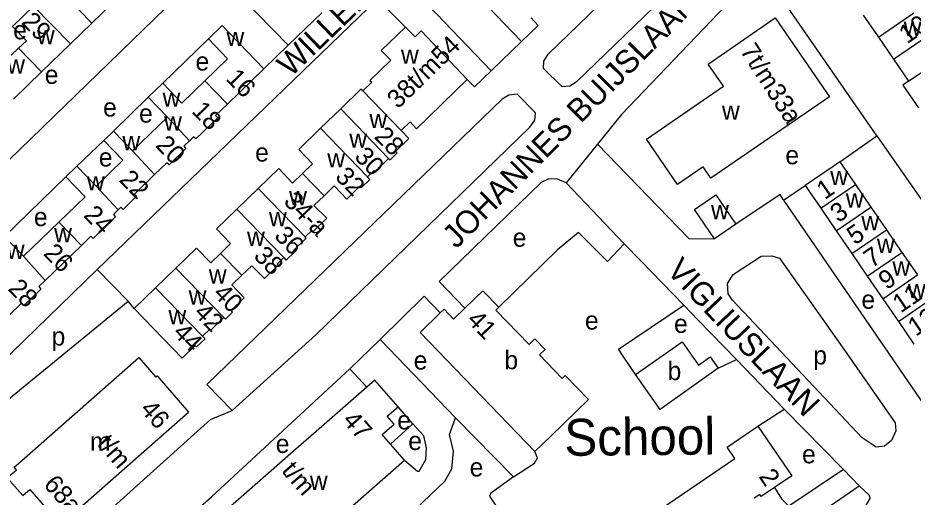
# Model space of a CAD drawing. Extents: x 157569 to 159501, y 382907 to 384670.
# Drawn here: x 158323.4 to 158517.3, y 383846.2 to 383949.9 of the extents above; entities that cross this region are included whole.
import ezdxf

# ---------------------------------------------------------------- set-up
doc = ezdxf.new("R2010")
doc.units = 0
for name, color, linetype in [('BLT_Basislijn', 7, 'Continuous'), ('BLT_Bebouwing', 7, 'Continuous'), ('BLT_Bebouwing_beschrifting', 7, 'Continuous'), ('BLT_Centroide', 7, 'Continuous'), ('BLT_Huisnummer', 7, 'Continuous'), ('BLT_Huisnummer_ tussenligend', 7, 'Continuous'), ('BLT_Huisnummer_reeks', 7, 'Continuous'), ('BLT_Onderverdeling_panden', 7, 'Continuous'), ('BLT_Straatnaam', 7, 'Continuous'), ('BLT_Vlakafsluiter', 7, 'Continuous')]:
    doc.layers.add(name, color=color, linetype=linetype)

msp = doc.modelspace()

# ---------------------------------------------------------------- linework, layer by layer
at = {"layer": 'BLT_Basislijn'}
for p, q in [((158444.32, 383936.05), (158491.23, 383981.35)), ((158351.47, 383975.38), (158381.9, 383944.01)), ((158413.23, 383964.9), (158432.5, 383944.85)), ((158454.14, 383929.01), (158484.39, 383960.64)), ((158425.87, 383938.46), (158406.68, 383958.58)), ((158359.94, 383956.53), (158309.3, 383907.45)), ((158381.9, 383944.01), (158389.2, 383951.07)), ((158436.1, 383948.33), (158434.55, 383949.94)), ((158432.5, 383944.85), (158436.1, 383948.33)), ((158364.64, 383945.39), (158354.73, 383935.81)), ((158381.9, 383944.01), (158376.65, 383938.93)), ((158425.87, 383938.46), (158432.5, 383944.85)), ((158425.87, 383938.46), (158422.28, 383934.99)), ((158422.28, 383934.99), (158420.74, 383936.58)), ((158351.61, 383932.79), (158344.07, 383925.44)), ((158428.26, 383932.38), (158364.31, 383870.57)), ((158387.89, 383881.33), (158434.28, 383926.29)), ((158501.47, 383918.77), (158509.5, 383924.39)), ((158509.5, 383924.39), (158540.12, 383880.37)), ((158341.97, 383923.41), (158336.13, 383917.82)), ((158468.71, 383902.18), (158448.94, 383922.63)), ((158333.76, 383915.53), (158320.42, 383902.64)), ((158489.28, 383910.52), (158493.97, 383913.66)), ((158489.28, 383910.52), (158519.57, 383866.35)), ((158468.71, 383902.18), (158474.29, 383902.14)), ((158451.12, 383897.23), (158454.74, 383901.07)), ((158454.74, 383901.07), (158458.33, 383897.35)), ((158458.33, 383897.35), (158467.63, 383887.79)), ((158347.25, 383888.59), (158340.56, 383895.5)), ((158420.23, 383887.14), (158414.62, 383892.88)), ((158411.42, 383889.71), (158401.83, 383880.33)), ((158414.86, 383886.07), (158411.42, 383889.71)), ((158309.18, 383857.56), (158347.25, 383888.59)), ((158348.55, 383887.03), (158347.25, 383888.59)), ((158467.63, 383887.79), (158470.79, 383884.54)), ((158470.79, 383884.54), (158479.03, 383876)), ((158369.8, 383864.96), (158387.89, 383881.33)), ((158418.21, 383863.39), (158401.83, 383880.33)), ((158475.08, 383874.11), (158479.03, 383876)), ((158479.03, 383876), (158489.4, 383865.25)), ((158395.28, 383873.99), (158398.93, 383870.01)), ((158369.8, 383864.96), (158364.31, 383870.57)), ((158365.06, 383863.02), (158369.8, 383864.96)), ((158408.95, 383862.05), (158405.74, 383865.78)), ((158483.71, 383861.56), (158489.4, 383865.25)), ((158502.26, 383852.17), (158489.4, 383865.25)), ((158418.21, 383863.39), (158430.73, 383850.57)), ((158408.95, 383862.05), (158404.09, 383857.67)), ((158502.26, 383852.17), (158490.4, 383844.22)), ((158505.61, 383848.66), (158502.26, 383852.17))]:
    msp.add_line(p, q, dxfattribs=at)
for points in [[(158438.28, 383942.1), (158537.6, 384038.11), (158531.85, 384044.06)], [(158509.5, 383924.39), (158509.32, 383924.65), (158484.39, 383960.64)], [(158340.56, 383895.5), (158401.25, 383954.08), (158407.33, 383947.96)], [(158444.32, 383936.05), (158442.98, 383935.18), (158441.26, 383935), (158437.22, 383939.01), (158437.35, 383940.6), (158438.28, 383942.1)], [(158434.28, 383926.29), (158435.34, 383927.81), (158435.52, 383929.42), (158431.51, 383933.41), (158429.75, 383933.25), (158428.26, 383932.38)], [(158442.13, 383914.27), (158440.29, 383915.01), (158438.39, 383915.08), (158436.76, 383914.31), (158414.62, 383892.88)], [(158454.74, 383901.07), (158442.13, 383914.27)], [(158489.28, 383910.52), (158489.19, 383910.66), (158488.5, 383911.72), (158478.89, 383905.29)], [(158451.12, 383897.23), (158444.84, 383903.51), (158440.31, 383899.76), (158427.56, 383887.29)], [(158502.47, 383878.02), (158513.46, 383862.31), (158513.62, 383860.58), (158512.66, 383858.5), (158511.12, 383857.21), (158509.3, 383857.05), (158506.27, 383859.05), (158478.22, 383888.82), (158477.23, 383890.18), (158477.09, 383892.43), (158478.32, 383894.38), (158484.39, 383898.34), (158486.69, 383898.42), (158488.38, 383897.95), (158502.47, 383878.02)], [(158340.56, 383895.5), (158306.05, 383862.05), (158309.18, 383857.56)], [(158457.21, 383872.74), (158453.49, 383878.22), (158467.63, 383887.79)], [(158342.01, 383826.07), (158342.71, 383826.37), (158365.34, 383846.3), (158395.28, 383873.99)], [(158318.74, 383825.56), (158321.24, 383825.28), (158324.51, 383826.85), (158332.42, 383833.63), (158365.06, 383863.02)], [(158403.38, 383834.19), (158402.8, 383834.97), (158402.65, 383836.33), (158406.4, 383840.67), (158415.84, 383849.67), (158417.41, 383852.34), (158417.78, 383856.17), (158416.9, 383859.74), (158418.21, 383863.39)], [(158407.11, 383854.22), (158409.91, 383851.85), (158410.33, 383851.82), (158411.76, 383854.37), (158411.9, 383856.9), (158411.28, 383859.5), (158408.95, 383862.05)], [(158430.73, 383850.57), (158435.29, 383853.55), (158435.95, 383854.74), (158435.37, 383856.09)], [(158430.73, 383850.57), (158425.77, 383846.97), (158425.55, 383846.43), (158432.02, 383836.7), (158447.4, 383814.83)], [(158445, 383801.93), (158444.68, 383803.12), (158444.68, 383804.84), (158446.2, 383807.43), (158453.05, 383812.44), (158505.61, 383848.66)], [(158445, 383801.93), (158474.43, 383822.14), (158502.43, 383840.92), (158507, 383844.19), (158508.01, 383845.93), (158507.87, 383846.59), (158505.61, 383848.66)], [(158487.33, 383848.28), (158488.81, 383845.86), (158490.4, 383844.22)]]:
    msp.add_lwpolyline(points, dxfattribs=at)
at = {"layer": 'BLT_Bebouwing'}
for p, q in [((158322.2, 383948.1), (158326.74, 383952.49)), ((158344.07, 383953.36), (158339.4, 383948.83)), ((158506.54, 383950.51), (158509.81, 383945.75)), ((158325.19, 383944.98), (158322.2, 383948.1)), ((158339.4, 383948.83), (158334.73, 383944.32)), ((158364.64, 383945.39), (158367.63, 383948.28)), ((158367.63, 383948.28), (158376.65, 383938.93)), ((158407.33, 383947.96), (158402.08, 383942.89)), ((158409.41, 383945.87), (158407.33, 383947.96)), ((158410.71, 383947.11), (158409.41, 383945.87)), ((158420.74, 383936.58), (158410.71, 383947.11)), ((158509.81, 383945.75), (158513.08, 383940.99)), ((158323.5, 383943.36), (158325.19, 383944.98)), ((158334.73, 383944.32), (158328.48, 383938.27)), ((158368.81, 383941.08), (158364.64, 383945.39)), ((158321.91, 383941.85), (158323.5, 383943.36)), ((158402.08, 383942.89), (158404.15, 383940.79)), ((158363.89, 383936.32), (158368.81, 383941.08)), ((158404.15, 383940.79), (158399.63, 383936.41)), ((158513.08, 383940.99), (158516.36, 383936.23)), ((158328.48, 383938.27), (158322.39, 383932.38)), ((158376.65, 383938.93), (158368.74, 383931.29)), ((158358.9, 383931.5), (158363.89, 383936.32)), ((158400.02, 383936.01), (158398.09, 383934.15)), ((158399.63, 383936.41), (158400.02, 383936.01)), ((158409.75, 383925.96), (158420.74, 383936.58)), ((158351.61, 383932.79), (158354.73, 383935.81)), ((158354.73, 383935.81), (158358.9, 383931.5)), ((158397.7, 383934.54), (158393.3, 383930.29)), ((158398.09, 383934.15), (158397.7, 383934.54)), ((158355.76, 383928.46), (158351.61, 383932.79)), ((158368.74, 383931.29), (158366.2, 383928.84)), ((158393.3, 383930.29), (158388.92, 383926.05)), ((158348.21, 383921.16), (158355.76, 383928.46)), ((158366.68, 383928.34), (158361.93, 383923.75)), ((158366.2, 383928.84), (158366.68, 383928.34)), ((158406.38, 383925.54), (158408.33, 383927.43)), ((158408.33, 383927.43), (158409.75, 383925.96)), ((158341.97, 383923.41), (158344.07, 383925.44)), ((158344.07, 383925.44), (158348.21, 383921.16)), ((158388.92, 383926.05), (158384.2, 383921.49)), ((158408.09, 383923.82), (158406.38, 383925.54)), ((158346.11, 383919.13), (158341.97, 383923.41)), ((158360.51, 383923.33), (158359.29, 383922.16)), ((158361.44, 383924.22), (158360.51, 383923.33)), ((158361.93, 383923.75), (158361.44, 383924.22)), ((158405.21, 383921.03), (158408.09, 383923.82)), ((158466.26, 383913.87), (158459.53, 383923.68)), ((158359.77, 383921.66), (158356.1, 383918.12)), ((158359.29, 383922.16), (158359.77, 383921.66)), ((158384.2, 383921.49), (158387.22, 383918.37)), ((158403.99, 383919.19), (158405.53, 383920.73)), ((158405.53, 383920.73), (158405.21, 383921.03)), ((158340.3, 383913.52), (158346.11, 383919.13)), ((158355.6, 383918.59), (158352.95, 383916.03)), ((158356.1, 383918.12), (158355.6, 383918.59)), ((158400.78, 383916.71), (158403.68, 383919.51)), ((158403.68, 383919.51), (158403.99, 383919.19)), ((158501.47, 383918.77), (158504.82, 383913.89)), ((158333.76, 383915.53), (158336.13, 383917.82)), ((158336.13, 383917.82), (158340.3, 383913.52)), ((158379.87, 383917.31), (158375.41, 383912.99)), ((158382.89, 383914.19), (158379.87, 383917.31)), ((158387.22, 383918.37), (158385.02, 383916.25)), ((158399.08, 383915.52), (158400.54, 383916.94)), ((158400.54, 383916.94), (158400.78, 383916.71)), ((158337.92, 383911.22), (158333.76, 383915.53)), ((158352.95, 383916.03), (158348.6, 383911.82)), ((158385.02, 383916.25), (158382.89, 383914.19)), ((158397.77, 383913.19), (158399.58, 383914.95)), ((158399.58, 383914.95), (158399.08, 383915.52)), ((158375.41, 383912.99), (158370.78, 383908.52)), ((158389.69, 383911.46), (158391.9, 383913.56)), ((158391.9, 383913.56), (158394.63, 383910.74)), ((158394.63, 383910.74), (158397.45, 383913.5)), ((158397.45, 383913.5), (158397.77, 383913.19)), ((158493.97, 383913.66), (158497.33, 383908.76)), ((158504.82, 383913.89), (158508.19, 383908.99)), ((158332.25, 383905.74), (158337.92, 383911.22)), ((158349.06, 383911.33), (158346.14, 383908.5)), ((158348.6, 383911.82), (158349.06, 383911.33)), ((158387.48, 383909.36), (158389.69, 383911.46)), ((158345.67, 383908.98), (158345.06, 383908.39)), ((158346.14, 383908.5), (158345.67, 383908.98)), ((158390.29, 383906.58), (158387.48, 383909.36)), ((158508.19, 383908.99), (158511.56, 383904.09)), ((158344.5, 383906.9), (158339.64, 383902.21)), ((158345.06, 383908.39), (158344.05, 383907.41)), ((158344.05, 383907.41), (158344.5, 383906.9)), ((158370.78, 383908.52), (158366.37, 383904.25)), ((158497.33, 383908.76), (158500.69, 383903.85)), ((158324.59, 383898.34), (158332.25, 383905.74)), ((158387.31, 383903.72), (158390.29, 383906.58)), ((158366.37, 383904.25), (158369.46, 383901.08)), ((158385.62, 383902.53), (158387.08, 383903.95)), ((158387.08, 383903.95), (158387.31, 383903.72)), ((158500.69, 383903.85), (158504.05, 383898.95)), ((158511.56, 383904.09), (158514.92, 383899.19)), ((158320.42, 383902.64), (158324.59, 383898.34)), ((158339.16, 383902.68), (158337.11, 383900.71)), ((158339.64, 383902.21), (158339.16, 383902.68)), ((158369.46, 383901.08), (158367.27, 383898.96)), ((158383.04, 383899.59), (158385.83, 383902.28)), ((158385.83, 383902.28), (158385.62, 383902.53)), ((158337.11, 383900.71), (158329.26, 383893.12)), ((158362.05, 383900.08), (158357.56, 383895.74)), ((158365.13, 383896.9), (158362.05, 383900.08)), ((158381.51, 383897.51), (158383.34, 383899.27)), ((158383.34, 383899.27), (158383.04, 383899.59)), ((158514.92, 383899.19), (158518.29, 383894.29)), ((158367.27, 383898.96), (158365.13, 383896.9)), ((158379.51, 383896.64), (158381, 383898.05)), ((158381, 383898.05), (158381.51, 383897.51)), ((158504.05, 383898.95), (158507.41, 383894.05)), ((158357.56, 383895.74), (158353.16, 383891.49)), ((158371.9, 383894.22), (158374.06, 383896.3)), ((158374.06, 383896.3), (158376.77, 383893.51)), ((158376.77, 383893.51), (158379.73, 383896.4)), ((158379.73, 383896.4), (158379.51, 383896.64)), ((158369.73, 383892.14), (158371.9, 383894.22)), ((158507.41, 383894.05), (158510.77, 383889.14)), ((158329.26, 383893.12), (158327.87, 383891.77)), ((158327.87, 383891.77), (158328.31, 383891.25)), ((158353.16, 383891.49), (158348.55, 383887.03)), ((158372.42, 383889.32), (158369.73, 383892.14)), ((158328.31, 383891.25), (158324.65, 383887.7)), ((158324.15, 383888.18), (158321.3, 383885.42)), ((158324.65, 383887.7), (158324.15, 383888.18)), ((158369.59, 383886.58), (158372.42, 383889.32)), ((158510.77, 383889.14), (158514.14, 383884.24)), ((158348.55, 383887.03), (158358.94, 383876.27)), ((158368.31, 383884.72), (158369.89, 383886.26)), ((158369.89, 383886.26), (158369.59, 383886.58)), ((158365.09, 383882.24), (158367.98, 383885.06)), ((158367.98, 383885.06), (158368.31, 383884.72)), ((158514.14, 383884.24), (158517.49, 383879.34)), ((158363.37, 383881.03), (158364.86, 383882.47)), ((158364.86, 383882.47), (158365.09, 383882.24)), ((158362.08, 383878.71), (158363.9, 383880.47)), ((158363.9, 383880.47), (158363.37, 383881.03)), ((158358.94, 383876.27), (158361.76, 383879.02)), ((158361.76, 383879.02), (158362.08, 383878.71)), ((158353.54, 383872.43), (158360.35, 383864.6)), ((158398.93, 383870.01), (158388, 383860.44)), ((158403.37, 383863.71), (158405.74, 383865.78)), ((158388, 383860.44), (158383.11, 383856.16)), ((158404.61, 383857.07), (158404.09, 383857.67)), ((158407.11, 383854.22), (158404.61, 383857.07)), ((158383.11, 383856.16), (158378.22, 383851.88)), ((158376.82, 383827.72), (158407.11, 383854.22)), ((158321.05, 383850.36), (158324.42, 383846.54))]:
    msp.add_line(p, q, dxfattribs=at)
for points in [[(158459.53, 383923.68), (158476.22, 383935.13), (158472.92, 383939.96), (158487.44, 383949.93), (158499.19, 383932.83), (158473.51, 383915.23), (158471.82, 383917.68), (158466.26, 383913.87)], [(158516.36, 383936.23), (158515.12, 383935.38), (158518.47, 383930.5)], [(158501.47, 383918.77), (158499.99, 383917.78), (158497.79, 383916.28), (158493.97, 383913.66)], [(158469.96, 383908.47), (158474.56, 383911.62), (158478.89, 383905.29)], [(158474.29, 383902.14), (158469.96, 383908.47)], [(158478.89, 383905.29), (158474.29, 383902.14)], [(158420.23, 383887.14), (158424.1, 383890.88), (158427.56, 383887.29)], [(158435.37, 383856.09), (158410.52, 383881.87), (158414.86, 383886.07)], [(158414.86, 383886.07), (158415.69, 383886.87), (158417.74, 383884.74), (158420.23, 383887.14)], [(158427.56, 383887.29), (158426.94, 383886.7), (158434.12, 383879.25), (158435.4, 383880.48), (158437.61, 383878.19), (158436.37, 383876.99), (158441.28, 383871.9), (158441.97, 383872.57), (158447.02, 383867.33)], [(158457.21, 383872.74), (158467.3, 383879.81), (158470.83, 383874.77), (158473.37, 383876.55), (158475.08, 383874.11)], [(158321.05, 383850.36), (158323.07, 383852.14), (158322.58, 383852.7), (158323.57, 383853.57), (158349.57, 383876.4), (158353.24, 383872.18), (158353.54, 383872.43)], [(158475.08, 383874.11), (158462.52, 383865.16), (158457.21, 383872.74)], [(158405.74, 383865.78), (158400.69, 383871.55), (158398.93, 383870.01)], [(158447.02, 383867.33), (158438.8, 383859.4), (158435.37, 383856.09)], [(158324.42, 383846.54), (158325.91, 383847.84), (158332.56, 383840.24), (158360.35, 383864.6)], [(158404.09, 383857.67), (158402.29, 383859.73), (158404.87, 383861.99), (158403.37, 383863.71)], [(158449.09, 383822.93), (158447.46, 383821.81), (158442.11, 383829.64), (158446.24, 383832.46), (158478.68, 383854.6), (158477.04, 383857.01), (158479.58, 383858.74), (158483.71, 383861.56)], [(158483.71, 383861.56), (158491.04, 383850.81), (158487.33, 383848.28)], [(158378.22, 383851.88), (158365.85, 383841.06), (158364.47, 383842.64)], [(158487.33, 383848.28), (158484.44, 383846.31), (158484.12, 383846.78), (158482.91, 383845.96)]]:
    msp.add_lwpolyline(points, dxfattribs=at)
at = {"layer": 'BLT_Onderverdeling_panden'}
for p, q in [((158339.4, 383948.83), (158331.42, 383957.01)), ((158326.74, 383952.49), (158334.73, 383944.32)), ((158509.81, 383945.75), (158517.51, 383951.05)), ((158513.08, 383940.99), (158520.78, 383946.29)), ((158323.5, 383943.36), (158328.48, 383938.27)), ((158516.36, 383936.23), (158522.8, 383940.66)), ((158368.74, 383931.29), (158363.89, 383936.32)), ((158398.09, 383934.15), (158406.38, 383925.54)), ((158393.3, 383930.29), (158403.68, 383919.51)), ((158355.76, 383928.46), (158360.51, 383923.33)), ((158399.08, 383915.52), (158388.92, 383926.05)), ((158352.95, 383916.03), (158348.21, 383921.16)), ((158385.02, 383916.25), (158389.69, 383911.46)), ((158340.3, 383913.52), (158345.06, 383908.39)), ((158385.62, 383902.53), (158375.41, 383912.99)), ((158497.33, 383908.76), (158504.82, 383913.89)), ((158500.69, 383903.85), (158508.19, 383908.99)), ((158370.78, 383908.52), (158381, 383898.05)), ((158332.25, 383905.74), (158337.11, 383900.71)), ((158504.05, 383898.95), (158511.56, 383904.09)), ((158507.41, 383894.05), (158514.92, 383899.19)), ((158329.26, 383893.12), (158324.59, 383898.34)), ((158367.27, 383898.96), (158371.9, 383894.22)), ((158367.98, 383885.06), (158357.56, 383895.74)), ((158510.77, 383889.14), (158518.29, 383894.29)), ((158353.16, 383891.49), (158363.37, 383881.03)), ((158514.14, 383884.24), (158521.65, 383889.39))]:
    msp.add_line(p, q, dxfattribs=at)
at = {"layer": 'BLT_Vlakafsluiter'}
for p, q in [((158454.14, 383929.01), (158448.94, 383922.63)), ((158448.94, 383922.63), (158442.13, 383914.27)), ((158395.28, 383873.99), (158401.83, 383880.33))]:
    msp.add_line(p, q, dxfattribs=at)

# ---------------------------------------------------------------- texts
at = {"layer": 'BLT_Bebouwing_beschrifting'}
msp.add_text('School', height=8, rotation=0.5505, dxfattribs=at).set_placement((158441.79, 383855.13))
at = {"layer": 'BLT_Centroide'}
for s, p in [('e', (158322.34, 383945.3)), ('w', (158515.3, 383946.03)), ('w', (158327.48, 383944.23)), ('w', (158368.55, 383943.85)), ('w', (158406.36, 383940)), ('w', (158321.03, 383937.88)), ('e', (158361.85, 383938.54)), ('e', (158329.18, 383935.66)), ('w', (158354.7, 383930.71)), ('e', (158341.82, 383928.59)), ('e', (158349.61, 383927.28)), ('w', (158475.91, 383927.89)), ('w', (158355.03, 383925.53)), ('w', (158399.52, 383926.08)), ('w', (158346, 383921.29)), ('w', (158395.16, 383921.83)), ('e', (158340.89, 383917.77)), ('e', (158374.76, 383918.84)), ('w', (158390.39, 383917.56)), ('e', (158489.65, 383918.26)), ('w', (158499.38, 383913.75)), ('w', (158338.3, 383912.59)), ('w', (158382.12, 383909.39)), ('w', (158502.76, 383908.88)), ('w', (158473.55, 383906.34)), ('e', (158326.82, 383904.87)), ('w', (158377.75, 383904.84)), ('w', (158506.12, 383903.97)), ('w', (158331.2, 383901.36)), ('w', (158373, 383900.59)), ('e', (158430.58, 383900.4)), ('w', (158509.49, 383899.06)), ('w', (158320.95, 383897.76)), ('w', (158512.85, 383894.16)), ('w', (158364.72, 383892.41)), ('w', (158516.21, 383889.28)), ('w', (158360.36, 383887.88)), ('e', (158506.13, 383886.98)), ('w', (158355.98, 383883.61)), ('e', (158446.22, 383882.47)), ('e', (158465.53, 383881.76)), ('p', (158330.66, 383879.02)), ('b', (158428.77, 383873.88)), ('p', (158495.7, 383874.92)), ('e', (158409.12, 383873.83)), ('b', (158464.13, 383871.54)), ('e', (158405.55, 383860.87)), ('m', (158338.99, 383856.26)), ('e', (158379.23, 383855.77)), ('e', (158407.94, 383856.4)), ('e', (158493.27, 383853.52)), ('e', (158421.25, 383850.69)), ('w', (158386.62, 383847.78))]:
    msp.add_text(s, height=4, dxfattribs=at).set_placement(p)
at = {"layer": 'BLT_Huisnummer'}
for s, rotation, p in [('29', 314.2979, (158323.91, 383948.88)), ('10', 34.4962, (158516.04, 383944.22)), ('16', 314.1628, (158368.23, 383936.62)), ('20', 314.1628, (158352.96, 383922.19)), ('28', 314.2979, (158400.38, 383924.07)), ('32', 314.2979, (158391.89, 383915.34)), ('1', 34.4274, (158498.19, 383910.47)), ('24', 314.1628, (158337.37, 383907.05)), ('5', 34.4274, (158504.73, 383900.67)), ('38', 314.2979, (158374.24, 383898.2)), ('9', 34.4274, (158511.58, 383890.96)), ('28', 314.1628, (158321.02, 383891.16)), ('40', 314.2979, (158365.45, 383890.05)), ('41', 313.9603, (158420.44, 383884.34)), ('13', 34.4274, (158517.95, 383880.89)), ('44', 314.298, (158356.72, 383881.59)), ('2', 304.3087, (158483.77, 383850.66))]:
    msp.add_text(s, height=4, rotation=rotation, dxfattribs=at).set_placement(p)
at = {"layer": 'BLT_Huisnummer_ tussenligend'}
for s, rotation, p in [('18', 314.1628, (158360.83, 383929.59)), ('30', 314.2979, (158396.07, 383919.68)), ('22', 314.1628, (158345.11, 383914.72)), ('3', 34.4274, (158501.13, 383905.49)), ('36', 314.2979, (158378.7, 383902.56)), ('26', 314.1628, (158328.69, 383898.78)), ('7', 34.4274, (158508.38, 383895.7)), ('11', 34.4274, (158514.64, 383885.94)), ('42', 314.2979, (158361.27, 383885.91))]:
    msp.add_text(s, height=4, rotation=rotation, dxfattribs=at).set_placement(p)
at = {"layer": 'BLT_Huisnummer_reeks'}
for s, rotation, p in [('38t/m54', 44.2979, (158405.71, 383930.09)), ('7t/m33a', 302.6127, (158479.74, 383942.84)), ('34-a', 314.2979, (158380.73, 383910.02)), ('46', 310.8955, (158349.66, 383865.12)), ('47', 311.1887, (158393.5, 383862.71)), ('t/m', 310.8965, (158340.32, 383857.66)), ('t/m', 310.7188, (158380.32, 383851.84)), ('68a', 311.2128, (158328.73, 383848.83))]:
    msp.add_text(s, height=4, rotation=rotation, dxfattribs=at).set_placement(p)
at = {"layer": 'BLT_Straatnaam'}
for s, height, rotation, p in [('WILLEM POMPESTRAAT', 5, 43.9902, (158382.49, 383936.96)), ('VAN DER MUYDENSTRAAT', 5, 304.4415, (158506.97, 383976.37)), ('JOHANNES BUIJSLAAN', 4.9999, 45.1626, (158418.36, 383899.81)), ('VIGLIUSLAAN', 5, 313.5432, (158463.69, 383895.05))]:
    msp.add_text(s, height=height, rotation=rotation, dxfattribs=at).set_placement(p)

doc.saveas('drawing.dxf')
